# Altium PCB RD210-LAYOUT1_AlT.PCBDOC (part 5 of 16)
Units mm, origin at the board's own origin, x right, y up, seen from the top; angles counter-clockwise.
Board outline 330 x 300 mm, 6 copper layers (TOP, Mid-Layer 1, Mid-Layer 2, Mid-Layer 3, Mid-Layer 4, BOTTOM), stack 1.422 mm thick; 981 components, 463 nets, 2326 pads, 12534 vias.
Unrouted connection lines stored in the file: 6.
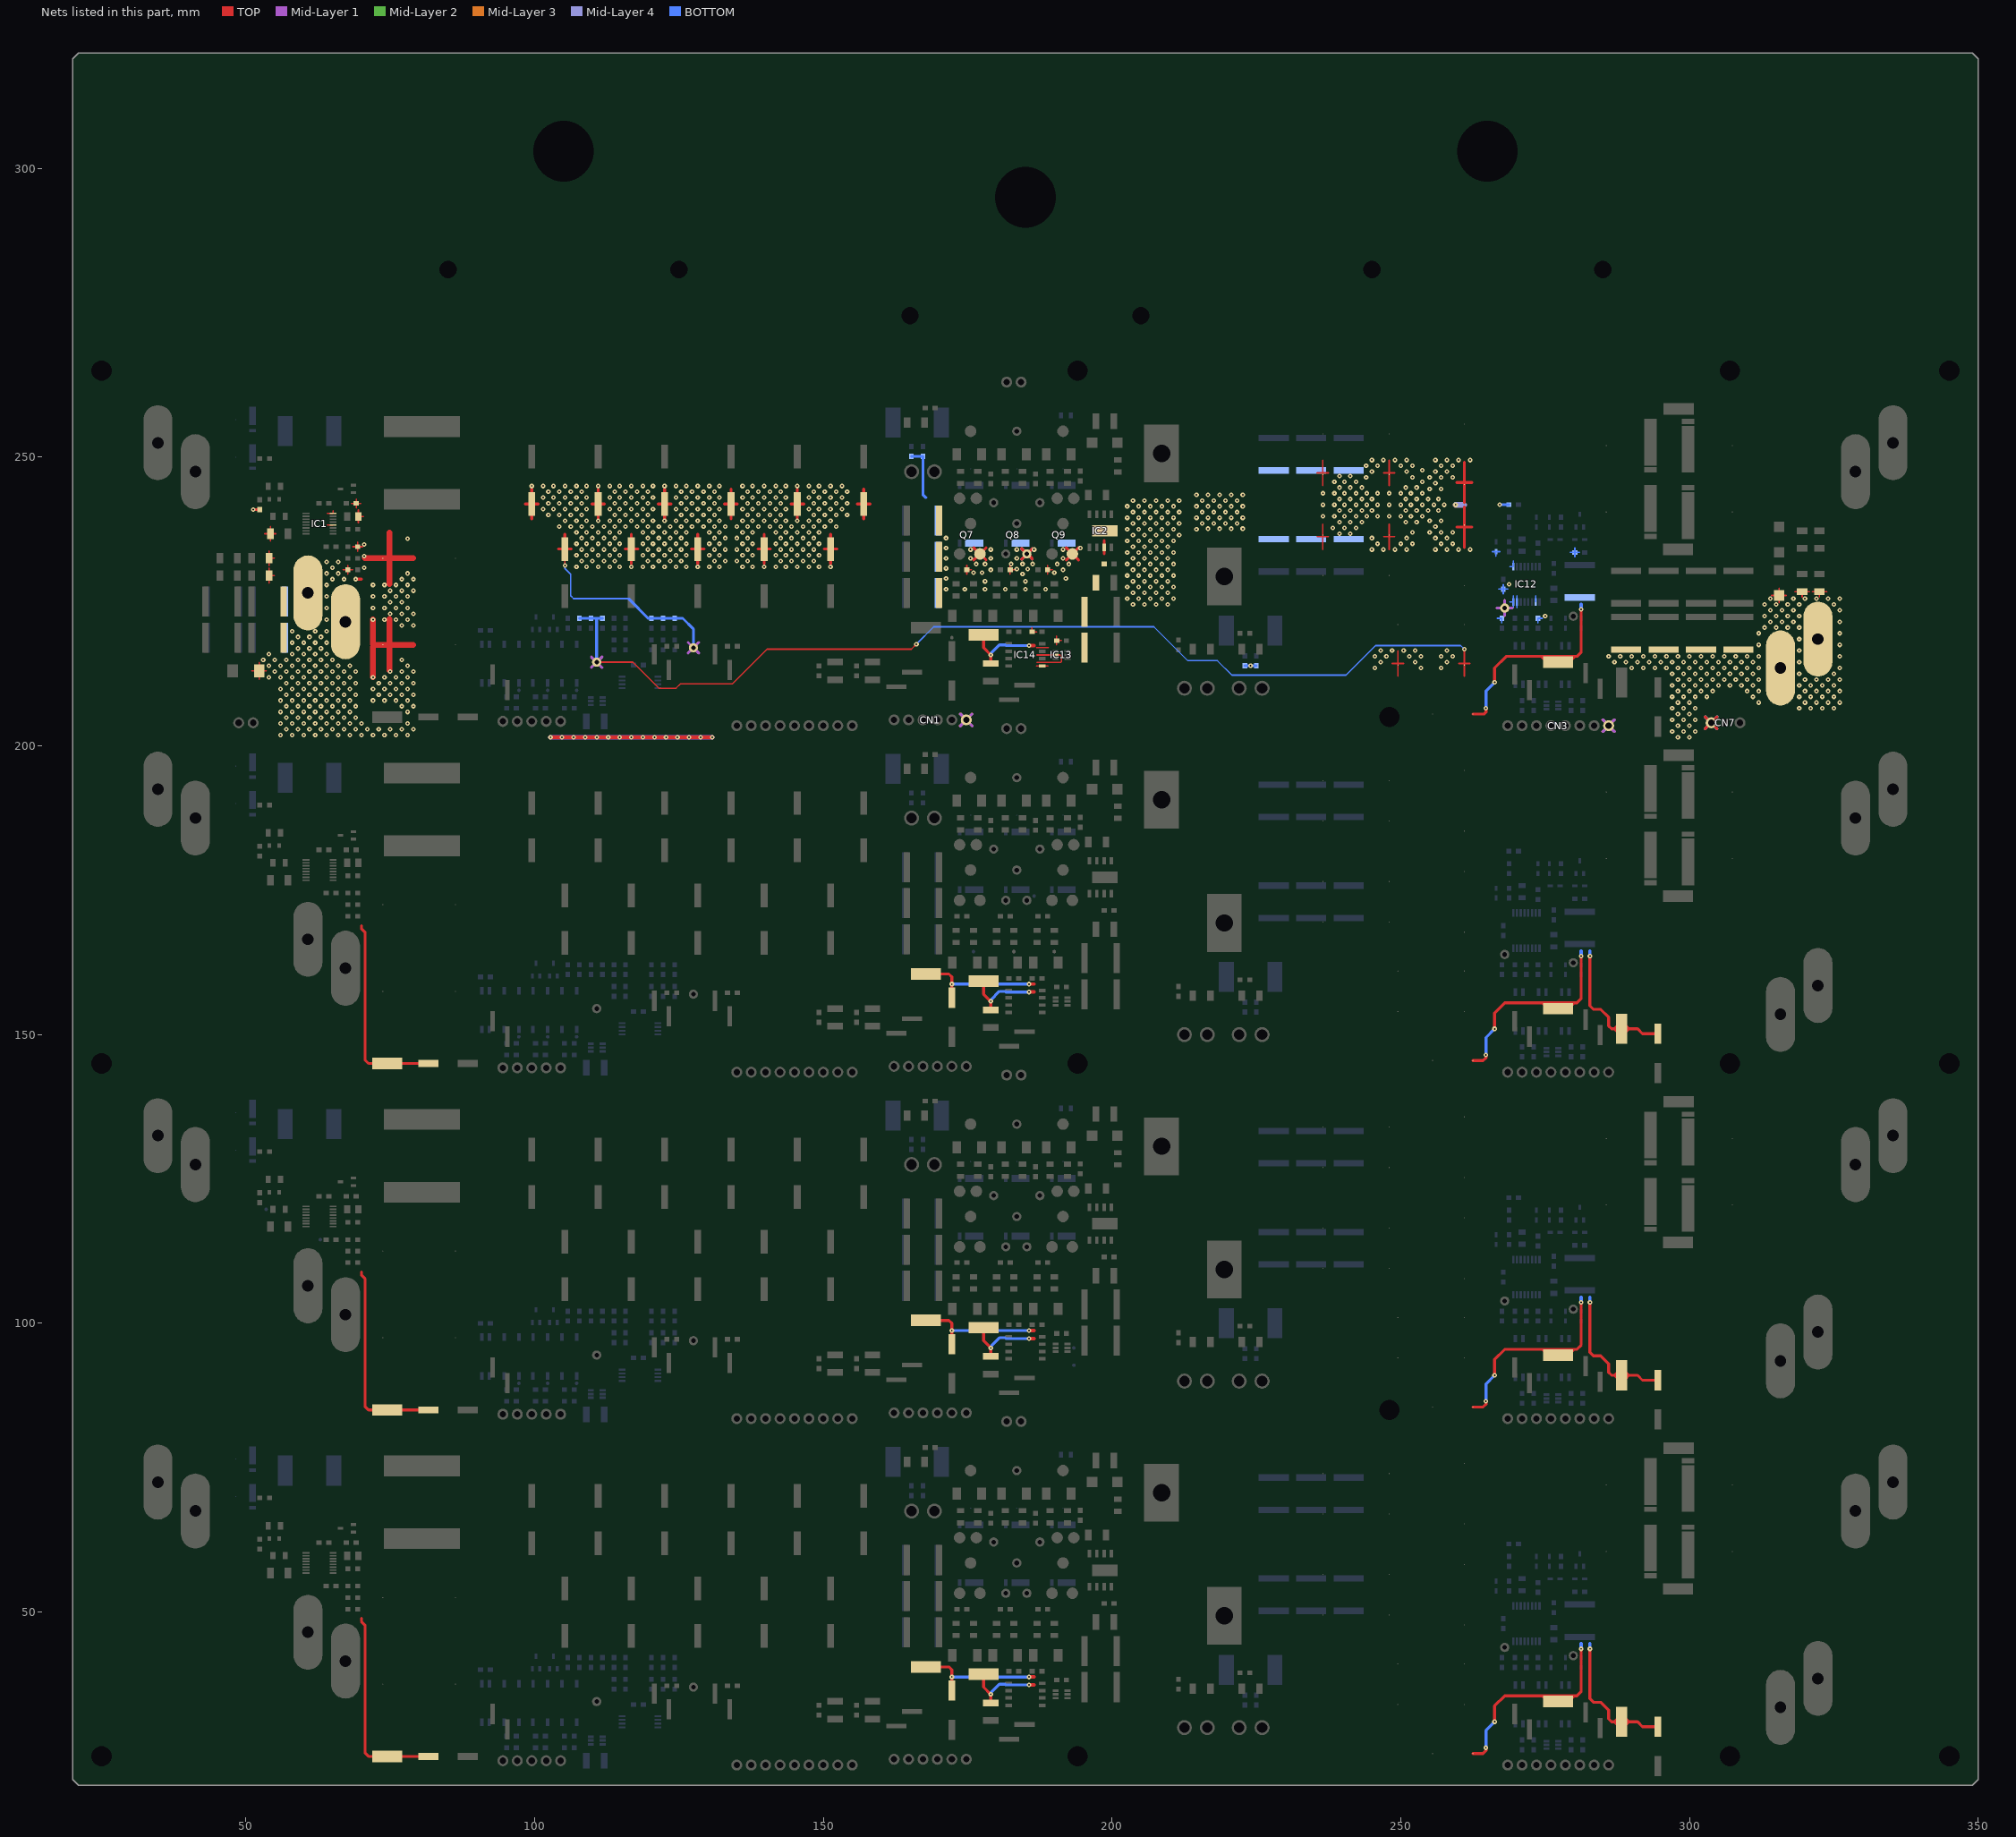
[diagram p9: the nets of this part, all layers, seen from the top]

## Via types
v1: diameter 0.8, hole 0.3, TOP to BOTTOM, 12534 vias

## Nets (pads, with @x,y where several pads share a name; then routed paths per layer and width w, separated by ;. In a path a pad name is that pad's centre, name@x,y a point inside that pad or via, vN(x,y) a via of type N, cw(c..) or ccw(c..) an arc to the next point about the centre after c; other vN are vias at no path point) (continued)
GND_5V_I1_0: C198.2 CN127.1 | length 22.6
  TOP w0.5: CN127.1@167.75,160.5 171.75,160.5 172.25,160 v1(172.25,158.75) C198.2@172.25,156.4
  TOP w0.6: v1(185.625,158.75) 186.5,158.75
  BOTTOM w0.5: v1(172.25,158.75) v1(185.625,158.75)
GND_5V_I1_1: C170.2 CN125.1 | length 32.8
  TOP w0.5: v1(282.75,163.625) 282.75,155 283.375,154.375 284.625,154.375 286,153 286,151.5 286.5,151 287,151 ; C170.2@294.5,150.15 291.85,150.15 291,151 289.5,151 ; 287,151 288,150 CN125.1@288.25,150 ; 287,151 288,152 CN125.1@288.25,152 ; 287,151 CN125.1@288.25,151 ; CN125.1@288.25,150 288.5,150 288.875,150.375 289.5,151 ; CN125.1@288.25,150 CN125.1@288.25,151 ; CN125.1@288.25,151 289.5,151 ; CN125.1@288.25,151 CN125.1@288.25,152 ; CN125.1@288.25,152 288.5,152 288.875,151.625 289.5,151
  BOTTOM w0.6: v1(282.75,163.625) 282.75,164.5
GND_5V_I1_2: C197.2 CN126.1 | length 34.7
  TOP w0.5: 70,168.875 70,168.375 70.625,167.75 70.625,145.625 71.25,145 CN126.1@74.5,145 C197.2@81.6,145
GND_5V_I2_0: C298.2 CN227.1 | length 22.6
  TOP w0.5: CN227.1@167.75,100.5 171.75,100.5 172.25,100 v1(172.25,98.75) C298.2@172.25,96.4
  TOP w0.6: v1(185.625,98.75) 186.5,98.75
  BOTTOM w0.5: v1(172.25,98.75) v1(185.625,98.75)
GND_5V_I2_1: C270.2 CN225.1 | length 32.8
  TOP w0.5: v1(282.75,103.625) 282.75,95 283.375,94.375 284.625,94.375 286,93 286,91.5 286.5,91 287,91 ; C270.2@294.5,90.15 291.85,90.15 291,91 289.5,91 ; 287,91 288,90 CN225.1@288.25,90 ; 287,91 288,92 CN225.1@288.25,92 ; 287,91 CN225.1@288.25,91 ; CN225.1@288.25,90 288.5,90 288.875,90.375 289.5,91 ; CN225.1@288.25,90 CN225.1@288.25,91 ; CN225.1@288.25,91 289.5,91 ; CN225.1@288.25,91 CN225.1@288.25,92 ; CN225.1@288.25,92 288.5,92 288.875,91.625 289.5,91
  BOTTOM w0.6: v1(282.75,103.625) 282.75,104.5
GND_5V_I2_2: C297.2 CN226.1 | length 34.7
  TOP w0.5: 70,108.875 70,108.375 70.625,107.75 70.625,85.625 71.25,85 CN226.1@74.5,85 C297.2@81.6,85
GND_5V_I3_0: C398.2 CN327.1 | length 22.6
  TOP w0.5: CN327.1@167.75,40.5 171.75,40.5 172.25,40 v1(172.25,38.75) C398.2@172.25,36.4
  TOP w0.6: v1(185.625,38.75) 186.5,38.75
  BOTTOM w0.5: v1(172.25,38.75) v1(185.625,38.75)
GND_5V_I3_1: C370.2 CN325.1 | length 32.8
  TOP w0.5: v1(282.75,43.625) 282.75,35 283.375,34.375 284.625,34.375 286,33 286,31.5 286.5,31 287,31 ; C370.2@294.5,30.15 291.85,30.15 291,31 289.5,31 ; 287,31 288,32 CN325.1@288.25,32 ; 287,31 287.625,30.375 288,30 CN325.1@288.25,30 ; 287,31 CN325.1@288.25,31 ; CN325.1@288.25,30 288.5,30 288.875,30.375 289.5,31 ; CN325.1@288.25,30 CN325.1@288.25,31 ; CN325.1@288.25,31 289.5,31 ; CN325.1@288.25,31 CN325.1@288.25,32 ; CN325.1@288.25,32 288.5,32 288.875,31.625 289.5,31
  BOTTOM w0.6: v1(282.75,43.625) 282.75,44.5
GND_5V_I3_2: C397.2 CN326.1 | length 34.7
  TOP w0.5: 70,48.875 70,48.375 70.625,47.75 70.625,25.625 71.25,25 CN326.1@74.5,25 C397.2@81.6,25
GND_12R0_SYS_I0_0: C99.2 CN28.1 | length 13.9
  TOP w0.5: CN28.1@177.75,219.25 177.75,217 v1(179,215.75) C99.2@179,214.275
  TOP w0.6: v1(185.625,217.375) 186.5,217.375
  BOTTOM w0.5: v1(179,215.75) 179,216 180.5,217.5 181.5,217.5 181.625,217.375 v1(185.625,217.375)
GND_12R0_SYS_I0_1: C71.2 CN24.1 | length 41.6
  TOP w0.5: C71.2@262.5,205.5 264.375,205.5 264.75,205.875 v1(264.75,206.5) ; v1(266.25,211) 266.25,213.5 268.25,215.5 274.375,215.5 ; v1(281.25,223.625) 281.25,216.25 280.5,215.5 280.125,215.5 ; 274.375,215.5 280.125,215.5 ; 274.375,215.5 275.375,214.5 CN24.1@277.25,214.5 279.125,214.5 280.125,215.5
  BOTTOM w0.5: v1(264.75,206.5) 264.75,209.5 v1(266.25,211)
  BOTTOM w0.6: v1(281.25,223.625) 281.25,224.5
GND_12R0_SYS_I1_0: C199.2 CN128.1 | length 13.9
  TOP w0.5: CN128.1@177.75,159.25 177.75,157 v1(179,155.75) C199.2@179,154.275
  TOP w0.6: v1(185.625,157.375) 186.5,157.375
  BOTTOM w0.5: v1(179,155.75) 179,156 180.5,157.5 181.5,157.5 181.625,157.375 v1(185.625,157.375)
GND_12R0_SYS_I1_1: C171.2 CN124.1 | length 41.4
  TOP w0.5: C171.2@262.5,145.5 264.25,145.5 264.75,146 v1(264.75,146.5) ; v1(266.25,151) 266.25,153.75 268,155.5 274.5,155.5 ; v1(281.25,163.625) 281.25,156.25 280.5,155.5 280,155.5 ; 274.5,155.5 280,155.5 ; 274.5,155.5 275.5,154.5 CN124.1@277.25,154.5 279,154.5 280,155.5
  BOTTOM w0.5: v1(264.75,146.5) 264.75,149.5 v1(266.25,151)
  BOTTOM w0.6: v1(281.25,163.625) 281.25,164.5
GND_12R0_SYS_I2_0: C299.2 CN228.1 | length 13.9
  TOP w0.5: CN228.1@177.75,99.25 177.75,97 v1(179,95.75) C299.2@179,94.275
  TOP w0.6: v1(185.625,97.375) 186.5,97.375
  BOTTOM w0.5: v1(179,95.75) 179,96 180.5,97.5 181.5,97.5 181.625,97.375 v1(185.625,97.375)
GND_12R0_SYS_I2_1: C271.2 CN224.1 | length 41.4
  TOP w0.5: C271.2@262.5,85.5 264.25,85.5 264.75,86 v1(264.75,86.5) ; v1(266.25,91) 266.25,93.75 268,95.5 274.5,95.5 ; v1(281.25,103.625) 281.25,96.25 280.5,95.5 280,95.5 ; 274.5,95.5 280,95.5 ; 274.5,95.5 275.5,94.5 CN224.1@277.25,94.5 279,94.5 280,95.5
  BOTTOM w0.5: v1(264.75,86.5) 264.75,89.5 v1(266.25,91)
  BOTTOM w0.6: v1(281.25,103.625) 281.25,104.5
GND_12R0_SYS_I3_0: C399.2 CN328.1 | length 13.9
  TOP w0.5: CN328.1@177.75,39.25 177.75,37 v1(179,35.75) C399.2@179,34.275
  TOP w0.6: v1(185.625,37.375) 186.5,37.375
  BOTTOM w0.5: v1(179,35.75) 179,36 180.5,37.5 181.5,37.5 181.625,37.375 v1(185.625,37.375)
GND_12R0_SYS_I3_1: C371.2 CN324.1 | length 41.4
  TOP w0.5: C371.2@262.5,25.5 264.25,25.5 264.75,26 v1(264.75,26.5) ; v1(266.25,31) 266.25,33.75 268,35.5 274.5,35.5 ; v1(281.25,43.625) 281.25,36.25 280.5,35.5 280,35.5 ; 274.5,35.5 280,35.5 ; 274.5,35.5 275.5,34.5 CN324.1@277.25,34.5 279,34.5 280,35.5
  BOTTOM w0.5: v1(264.75,26.5) 264.75,29.5 v1(266.25,31)
  BOTTOM w0.6: v1(281.25,43.625) 281.25,44.5
GND_P-1: C2.1 C4.1 C6.1 C8.1 C10.1 C12.1 C13.1 C14.2 C15.1 C16.2 C17.2 C18.2 C19.2 C20.2 C21.2 C22.2 C23.2 C24.2 C25.2 C26.2 C27.2 C28.2 C29.1 C30.1 C31.1 C32.1 C33.1 C34.1 C35.1 C36.1 C37.2 C38.2 C39.1 C40.1 C42.2 C43.2 C49.2 C50.2 C51.2 C52.2 C53.2 C54.2 C55.2 C56.2 C57.2 C58.2 C59.1 C60.1 C61.1 C62.1 C63.1 C64.1 C79.1 C81.1 C83.2 C86.1 C88.1 C90.1 C92.1 C94.1 C96.1 C101.1 C440.2 C444.2 CN1.6 CN3.1 CN7.3 CN16.1 CN17.1 CN20.1 CN34.1 D1.1 D16.1 D17.1 IC1.12 IC1.16 IC2.7 IC2.9 IC12.2 IC12.7 IC12.8 IC12.9 IC13.2 IC14.5 Q7.S Q8.S Q9.S R4.1 R22.2 R25.2 R28.2 R50.2 R51.1 R57.2 R58.1 R65.1 R88.1 R89.1 R93.1 TN12.1 TN12.2 TN14.1 TN14.2 TP17.1 TP19.1 | length 704.9
  TOP w0.25: 51.025,213 D1.1@52.3,213 ; 52.3,211.525 D1.1@52.3,213 ; 52.3,214.475 D1.1@52.3,213 ; 53.275,236.75 C13.1@54.225,236.75 ; 53.575,213 D1.1@52.3,213 ; 54.025,228.225 C4.1@54.025,229.5 ; 54.025,230.775 C4.1@54.025,229.5 ; 54.025,231.225 C2.1@54.025,232.5 ; 54.025,233.775 C2.1@54.025,232.5 ; 54.225,235.475 C13.1@54.225,236.75 ; 54.225,238.025 C13.1@54.225,236.75 ; 54.975,229.5 C4.1@54.025,229.5 ; 54.975,232.5 C2.1@54.025,232.5 ; 55.175,236.75 C13.1@54.225,236.75 ; 64.125,238.25 IC1.12@65.1,238.25 ; 64.125,240.25 IC1.16@65.1,240.25 65.1,240.76 ; 66.825,230.5 R4.1@67.65,230.5 ; 67.65,229.725 R4.1@67.65,230.5 ; 67.65,231.275 R4.1@67.65,230.5 ; 68.275,242 R65.1@69.1,242 ; 68.475,230.5 R4.1@67.65,230.5 ; 68.525,234.5 C15.1@69.35,234.5 ; 69.1,241.225 R65.1@69.1,242 ; 69.1,242.775 R65.1@69.1,242 ; 69.35,233.725 C15.1@69.35,234.5 ; 69.35,235.275 C15.1@69.35,234.5 ; 69.475,238.65 C14.2@69.475,239.75 ; 69.475,240.85 C14.2@69.475,239.75 ; 69.925,242 R65.1@69.1,242 ; 70.175,234.5 C15.1@69.35,234.5 ; 70.375,239.75 C14.2@69.475,239.75 ; v1(105.25,231.25) C28.2@105.25,234.1 ; CN17.1@110.75,214.5 117,214.5 121.5,210 124.5,210 125.25,210.75 134.25,210.75 140.25,216.75 165.25,216.75 v1(166.125,217.625) ; 174.85,229.725 R22.2@174.85,230.5 ; 174.85,231.275 R22.2@174.85,230.5 ; 175.675,230.5 R22.2@174.85,230.5 ; 182.35,229.725 R25.2@182.35,230.5 ; v1@182.35,231.275 R25.2@182.35,230.5 ; v1@183.175,230.5 R25.2@182.35,230.5 ; 186.15,220.525 C40.1@186.15,219.75 186.975,219.75 ; 186.875,217.02 189,217.02 ; 186.925,213.845 IC14.5@187.9,213.845 188.875,213.845 ; 187,214.48 191.105,214.48 191.215,214.59 191.215,215.515 190.98,215.75 IC13.2@190.225,215.75 187,215.75 ; 188.85,229.725 R28.2@188.85,230.5 ; 188.85,231.275 R28.2@188.85,230.5 ; 189.675,230.5 R28.2@188.85,230.5 ; 190.4,217.475 C39.1@190.4,218.25 ; 190.4,219.025 C39.1@190.4,218.25 ; 191.225,218.25 C39.1@190.4,218.25 ; 235.523,236.225 236.5,236.225 ; 235.523,247.275 236.5,247.275 ; 236.5,234.023 236.5,236.225 ; 236.5,238.427 C53.2@236.5,236.5 236.5,236.225 ; 236.5,245.073 C51.2@236.5,247 236.5,247.275 ; 236.5,249.477 236.5,247.275 ; 237.477,236.225 236.5,236.225 ; 237.477,247.275 236.5,247.275 ; 247.023,236.225 248,236.225 ; 247.023,247.275 248,247.275 ; 248,234.023 248,236.225 ; 248,238.427 C54.2@248,236.5 248,236.225 ; 248,245.073 C52.2@248,247 248,247.275 ; 248,249.477 248,247.275 ; 248.523,214.275 249.5,214.275 ; 248.977,236.225 248,236.225 ; 248.977,247.275 248,247.275 ; 249.5,212.073 C55.2@249.5,214 249.5,214.275 ; 249.5,216.477 249.5,214.275 ; 250.477,214.275 249.5,214.275 ; 260.023,214.275 261,214.275 ; 261,212.073 C56.2@261,214 261,214.275 ; v1(261,216.75) 261,214.275 ; 261.977,214.275 261,214.275 ; 314.225,226.05 D16.1@315.5,226.05 ; 315.5,224.775 D16.1@315.5,226.05 ; 315.5,227.325 D16.1@315.5,226.05 ; 316.775,226.05 D16.1@315.5,226.05 ; 318.225,226.725 C86.1@319.5,226.725 ; 319.5,225.775 C86.1@319.5,226.725 ; 320.775,226.725 C86.1@319.5,226.725 ; 321.225,226.725 C88.1@322.5,226.725 ; 322.5,225.775 C88.1@322.5,226.725 ; 323.775,226.725 C88.1@322.5,226.725
  TOP w0.5: v1(51.242,240.925) C444.2@52.385,240.925 ; v1(69,228.875) 70,228.875 ; 98.4,241.9 C18.2@99.5,241.9 ; 99.5,239.35 C18.2@99.5,241.9 ; 99.5,244.45 C18.2@99.5,241.9 ; 100.6,241.9 C18.2@99.5,241.9 ; 104.15,234.1 C28.2@105.25,234.1 ; 105.25,236.65 C28.2@105.25,234.1 ; 106.35,234.1 C28.2@105.25,234.1 ; 109.9,241.9 C19.2@111,241.9 ; v1@111,239.35 C19.2@111,241.9 ; 111,244.45 C19.2@111,241.9 ; 112.1,241.9 C19.2@111,241.9 ; 115.65,234.1 C27.2@116.75,234.1 ; 116.75,231.55 C27.2@116.75,234.1 ; 116.75,236.65 C27.2@116.75,234.1 ; 117.85,234.1 C27.2@116.75,234.1 ; 121.4,241.9 C20.2@122.5,241.9 ; v1@122.5,239.35 C20.2@122.5,241.9 ; 122.5,244.45 C20.2@122.5,241.9 ; 123.6,241.9 C20.2@122.5,241.9 ; 127.15,234.1 C26.2@128.25,234.1 ; 128.25,231.55 C26.2@128.25,234.1 ; 128.25,236.65 C26.2@128.25,234.1 ; 129.35,234.1 C26.2@128.25,234.1 ; 132.9,241.9 C21.2@134,241.9 ; 134,239.35 C21.2@134,241.9 ; 134,244.45 C21.2@134,241.9 ; 135.1,241.9 C21.2@134,241.9 ; 138.65,234.1 C25.2@139.75,234.1 ; 139.75,231.55 C25.2@139.75,234.1 ; 139.75,236.65 C25.2@139.75,234.1 ; 140.85,234.1 C25.2@139.75,234.1 ; 144.4,241.9 C22.2@145.5,241.9 ; v1@145.5,239.35 C22.2@145.5,241.9 ; 145.5,244.45 C22.2@145.5,241.9 ; 146.6,241.9 C22.2@145.5,241.9 ; 150.15,234.1 C24.2@151.25,234.1 ; 151.25,231.55 C24.2@151.25,234.1 ; 151.25,236.65 C24.2@151.25,234.1 ; 152.35,234.1 C24.2@151.25,234.1 ; 155.9,241.9 C23.2@157,241.9 ; 157,239.35 C23.2@157,241.9 ; 157,244.45 C23.2@157,241.9 ; 158.1,241.9 C23.2@157,241.9 ; 176.064,232.189 TP17.1@177.125,233.25 ; 176.064,234.311 TP17.1@177.125,233.25 ; 178.186,232.189 TP17.1@177.125,233.25 ; 178.186,234.311 TP17.1@177.125,233.25 ; 184.331,232.331 CN34.1@185.25,233.25 ; 184.331,234.169 CN34.1@185.25,233.25 ; CN34.1@185.375,233.25 186.125,232.5 ; 186.169,232.331 CN34.1@185.25,233.25 ; v1@186.169,234.169 CN34.1@185.25,233.25 ; 192.064,232.189 TP19.1@193.125,233.25 ; 192.064,234.311 TP19.1@193.125,233.25 ; 194.186,232.189 TP19.1@193.125,233.25 ; v1@194.186,234.311 TP19.1@193.125,233.25 ; 198.635,233.25 IC2.7@198.635,234.4 198.635,235.55 ; 259.696,237.9 261,237.9 ; 259.696,245.6 261,245.6 ; 261,234.396 261,237.9 ; 261,241.404 C58.2@261,238.25 261,237.9 ; 261,242.096 C57.2@261,245.25 261,245.6 ; 261,249.104 261,245.6 ; 262.304,237.9 261,237.9 ; 262.304,245.6 261,245.6 ; 302.725,202.975 CN7.3@303.75,204 ; 302.725,205.025 CN7.3@303.75,204 ; 304.775,202.975 CN7.3@303.75,204 ; 304.775,205.025 CN7.3@303.75,204
  TOP w0.6: v1(102.75,201.5) v1(104.75,201.5) v1(106.75,201.5) v1(108.75,201.5) v1(110.75,201.5) v1(112.75,201.5) v1(114.75,201.5) v1(116.75,201.5) v1(118.75,201.5) v1(120.75,201.5) v1(122.75,201.5) v1(124.75,201.5) v1(126.75,201.5) v1(128.75,201.5) v1(130.75,201.5)
  TOP w1: v1@70.625,232.5 C16.2@73.7,232.5 74.85,232.5 ; v1(72,211.875) 72,217.125 72.375,217.5 ; v1(72,221.875) 72,217.625 72.125,217.5 72.375,217.5 ; v1@74.85,213.043 74.85,217.5 ; 74.85,221.957 74.85,217.5 ; 74.85,228.043 74.85,232.5 ; 74.85,236.957 74.85,232.5 ; 79,217.5 74.85,217.5 ; 79,232.5 74.85,232.5 ; 72.375,217.5 C17.2@73.7,217.5 74.85,217.5
  Mid-Layer 1 w0.5: 109.831,213.581 CN17.1@110.75,214.5 ; 109.831,215.419 CN17.1@110.75,214.5 ; 111.669,213.581 CN17.1@110.75,214.5 ; 111.669,215.419 CN17.1@110.75,214.5 ; 126.581,216.081 CN16.1@127.5,217 ; 126.581,217.919 CN16.1@127.5,217 ; 128.419,216.081 CN16.1@127.5,217 ; 128.419,217.919 CN16.1@127.5,217 ; 173.725,203.475 CN1.6@174.75,204.5 ; 173.725,205.525 CN1.6@174.75,204.5 ; 175.775,203.475 CN1.6@174.75,204.5 ; 175.775,205.525 CN1.6@174.75,204.5 ; 184.331,232.331 CN34.1@185.25,233.25 ; 184.331,234.169 CN34.1@185.25,233.25 ; 186.169,232.331 CN34.1@185.25,233.25 ; v1@186.169,234.169 CN34.1@185.25,233.25 ; 266.7,223.875 CN20.1@268,223.875 ; 268,222.575 CN20.1@268,223.875 ; 268,225.175 CN20.1@268,223.875 ; 269.3,223.875 CN20.1@268,223.875 ; 284.975,202.475 CN3.1@286,203.5 ; 284.975,204.525 CN3.1@286,203.5 ; 287.025,202.475 CN3.1@286,203.5 ; 287.025,204.525 CN3.1@286,203.5 ; 302.725,202.975 CN7.3@303.75,204 ; 302.725,205.025 CN7.3@303.75,204 ; 304.775,202.975 CN7.3@303.75,204 ; 304.775,205.025 CN7.3@303.75,204
  Mid-Layer 1 w0.8: v1(102.75,201.5) v1(104.75,201.5) v1(106.75,201.5) v1(108.75,201.5) v1(110.75,201.5) v1(112.75,201.5) v1(114.75,201.5) v1(116.75,201.5) v1(118.75,201.5) v1(120.75,201.5) v1(122.75,201.5) v1(124.75,201.5) v1(126.75,201.5) v1(128.75,201.5) v1(130.75,201.5)
  Mid-Layer 2 w0.5: 173.725,203.475 CN1.6@174.75,204.5 ; 173.725,205.525 CN1.6@174.75,204.5 ; 175.775,203.475 CN1.6@174.75,204.5 ; 175.775,205.525 CN1.6@174.75,204.5 ; 184.331,232.331 CN34.1@185.25,233.25 ; 184.331,234.169 CN34.1@185.25,233.25 ; 186.169,232.331 CN34.1@185.25,233.25 ; v1@186.169,234.169 CN34.1@185.25,233.25 ; 266.7,223.875 CN20.1@268,223.875 ; 268,222.575 CN20.1@268,223.875 ; 268,225.175 CN20.1@268,223.875 ; 269.3,223.875 CN20.1@268,223.875 ; 284.975,202.475 CN3.1@286,203.5 ; 284.975,204.525 CN3.1@286,203.5 ; 287.025,202.475 CN3.1@286,203.5 ; 287.025,204.525 CN3.1@286,203.5 ; 302.725,202.975 CN7.3@303.75,204 ; 302.725,205.025 CN7.3@303.75,204 ; 304.775,202.975 CN7.3@303.75,204 ; 304.775,205.025 CN7.3@303.75,204
  Mid-Layer 3 w0.5: 173.725,203.475 CN1.6@174.75,204.5 ; 173.725,205.525 CN1.6@174.75,204.5 ; 175.775,203.475 CN1.6@174.75,204.5 ; 175.775,205.525 CN1.6@174.75,204.5 ; 184.331,232.331 CN34.1@185.25,233.25 ; 184.331,234.169 CN34.1@185.25,233.25 ; 186.169,232.331 CN34.1@185.25,233.25 ; v1@186.169,234.169 CN34.1@185.25,233.25 ; 266.7,223.875 CN20.1@268,223.875 ; 268,222.575 CN20.1@268,223.875 ; 268,225.175 CN20.1@268,223.875 ; 269.3,223.875 CN20.1@268,223.875 ; 284.975,202.475 CN3.1@286,203.5 ; 284.975,204.525 CN3.1@286,203.5 ; 287.025,202.475 CN3.1@286,203.5 ; 287.025,204.525 CN3.1@286,203.5 ; 302.725,202.975 CN7.3@303.75,204 ; 302.725,205.025 CN7.3@303.75,204 ; 304.775,202.975 CN7.3@303.75,204 ; 304.775,205.025 CN7.3@303.75,204
  Mid-Layer 4 w1: v1(259.5,241.75) 261,241.75
  BOTTOM w0.25: v1(105.25,231.25) 105.25,230.75 106.25,229.75 106.25,226 106.75,225.5 116.25,225.5 116.375,225.375 ; v1(166.125,217.625) 169.125,220.625 207.25,220.625 213.125,214.75 218.25,214.75 220.75,212.25 240.5,212.25 245.625,217.375 260.375,217.375 v1(261,216.75) ; 265.875,233.65 D17.1@266.5,233.65 ; 266.5,232.825 D17.1@266.5,233.65 ; 266.725,222.1 R88.1@267.5,222.1 267.5,221.275 ; 266.975,227.15 C83.2@267.75,227.15 ; 267.125,233.65 D17.1@266.5,233.65 ; 267.75,226.325 C83.2@267.75,227.15 ; 267.75,227.975 C83.2@267.75,227.15 ; 268.525,227.15 C83.2@267.75,227.15 ; 268.9,224.95 IC12.8@269.475,224.95 ; 268.9,231.05 IC12.9@269.475,231.05 269.475,232.075 ; 269.475,223.925 IC12.8@269.475,224.95 ; 269.475,225.975 IC12.8@269.475,224.95 ; 270.125,223.925 IC12.7@270.125,224.95 270.125,225.975 ; IC12.2@273.375,224.95 273.375,225.975 ; 273.75,221.275 R89.1@273.75,222.1 274.525,222.1 ; 279.325,233.5 R93.1@280.15,233.5 ; 280.15,232.725 R93.1@280.15,233.5 ; 280.15,234.275 R93.1@280.15,233.5 ; 280.975,233.5 R93.1@280.15,233.5
  BOTTOM w0.5: C79.1@107.75,222.1 R57.2@109.75,222.1 110.5,222.1 ; CN17.1@110.75,214.5 110.75,221.85 ; R58.1@111.75,222.1 111,222.1 ; 116.375,225.375 119.65,222.1 R51.1@120.25,222.1 C101.1@122.25,222.1 R50.2@124.25,222.1 125.65,222.1 127.5,220.25 CN16.1@127.5,217 ; C43.2@165.25,250.15 C42.2@167.25,250.15 167.25,243.5 167.75,243 ; 184.331,232.331 CN34.1@185.25,233.25 ; 184.331,234.169 CN34.1@185.25,233.25 ; 186.169,232.331 CN34.1@185.25,233.25 ; v1@186.169,234.169 CN34.1@185.25,233.25 ; C49.2@223,213.9 v1(224,213.9) C50.2@225,213.9 ; 266.7,223.875 CN20.1@268,223.875 268,225.175 ; v1(267.142,241.775) C440.2@268.705,241.775 ; 110.5,222.1 110.75,221.85 ; 110.5,222.1 111,222.1 ; 110.75,221.85 111,222.1
  BOTTOM w0.6: v1(102.75,201.5) v1(104.75,201.5) v1(106.75,201.5) v1(108.75,201.5) v1(110.75,201.5) v1(112.75,201.5) v1(114.75,201.5) v1(116.75,201.5) v1(118.75,201.5) v1(120.75,201.5) v1(122.75,201.5) v1(124.75,201.5) v1(126.75,201.5) v1(128.75,201.5) v1(130.75,201.5)
  other v1: 298,201.5 300,201.5 56,201.875 58,201.875 60,201.875 62,201.875 64,201.875 66,201.875 68,201.875 70,201.875 72,201.875 74,201.875 76,201.875 78,201.875 297,202.5 299,202.5 301,202.5 57,202.875 59,202.875 61,202.875 63,202.875 65,202.875 67,202.875 69,202.875 71,202.875 73,202.875 75,202.875 77,202.875 79,202.875 298,203.5 300,203.5 56,203.875 58,203.875 60,203.875 62,203.875 64,203.875 66,203.875 68,203.875 70,203.875 78,203.875 297,204.5 299,204.5 301,204.5 57,204.875 59,204.875 61,204.875 63,204.875 65,204.875 67,204.875 69,204.875 298,205.5 300,205.5 56,205.875 58,205.875 60,205.875 62,205.875 64,205.875 66,205.875 68,205.875 78,205.875 297,206.5 299,206.5 301,206.5 319,206.5 321,206.5 323,206.5 325,206.5 57,206.875 59,206.875 61,206.875 63,206.875 65,206.875 67,206.875 69,206.875 77,206.875 79,206.875 298,207.5 300,207.5 312,207.5 320,207.5 322,207.5 324,207.5 326,207.5 56,207.875 58,207.875 60,207.875 62,207.875 64,207.875 66,207.875 68,207.875 72,207.875 74,207.875 76,207.875 78,207.875 297,208.5 299,208.5 301,208.5 303,208.5 311,208.5 319,208.5 321,208.5 323,208.5 325,208.5 57,208.875 59,208.875 61,208.875 63,208.875 65,208.875 67,208.875 69,208.875 73,208.875 75,208.875 77,208.875 79,208.875 298,209.5 300,209.5 302,209.5 304,209.5 310,209.5 312,209.5 320,209.5 322,209.5 324,209.5 326,209.5 56,209.875 58,209.875 60,209.875 62,209.875 64,209.875 66,209.875 68,209.875 72,209.875 74,209.875 76,209.875 78,209.875 297,210.5 299,210.5 301,210.5 303,210.5 305,210.5 307,210.5 309,210.5 311,210.5 319,210.5 321,210.5 323,210.5 325,210.5 57,210.875 59,210.875 61,210.875 63,210.875 65,210.875 67,210.875 69,210.875 73,210.875 75,210.875 77,210.875 79,210.875 298,211.5 300,211.5 302,211.5 304,211.5 306,211.5 308,211.5 310,211.5 312,211.5 320,211.5 322,211.5 324,211.5 326,211.5 54,211.875 56,211.875 58,211.875 60,211.875 62,211.875 64,211.875 66,211.875 68,211.875 74,211.875 76,211.875 78,211.875 297,212.5 299,212.5 301,212.5 303,212.5 305,212.5 307,212.5 309,212.5 311,212.5 319,212.5 325,212.5 55,212.875 57,212.875 59,212.875 61,212.875 63,212.875 65,212.875 67,212.875 69,212.875 75,212.875 77,212.875 79,212.875 245.5,213.5 253.5,213.5 257,213.5 290,213.5 292,213.5 294,213.5 296,213.5 298,213.5 300,213.5 302,213.5 304,213.5 306,213.5 308,213.5 310,213.5 312,213.5 326,213.5 54,213.875 56,213.875 58,213.875 60,213.875 62,213.875 64,213.875 66,213.875 68,213.875 78,213.875 246.5,214.5 252.5,214.5 258,214.5 287,214.5 289,214.5 291,214.5 293,214.5 295,214.5 297,214.5 299,214.5 301,214.5 303,214.5 305,214.5 307,214.5 309,214.5 311,214.5 319,214.5 53,214.875 55,214.875 57,214.875 59,214.875 61,214.875 63,214.875 65,214.875 77,214.875 245.5,215.5 247.5,215.5 251.5,215.5 253.5,215.5 257,215.5 259,215.5 286,215.5 288,215.5 290,215.5 292,215.5 294,215.5 296,215.5 298,215.5 300,215.5 302,215.5 304,215.5 306,215.5 308,215.5 310,215.5 312,215.5 326,215.5 54,215.875 58,215.875 60,215.875 62,215.875 64,215.875 246.5,216.5 248.5,216.5 250.5,216.5 252.5,216.5 258,216.5 319,216.5 59,216.875 61,216.875 63,216.875 312,217.5 326,217.5 58,217.875 60,217.875 62,217.875 64,217.875 319,218.5 59,218.875 61,218.875 63,218.875 312,219.5 326,219.5 58,219.875 62,219.875 64,219.875 313,220.5 315,220.5 317,220.5 319,220.5 77,220.875 79,220.875 314,221.5 316,221.5 318,221.5 326,221.5 64,221.875 74,221.875 76,221.875 78,221.875 275,222.5 313,222.5 315,222.5 317,222.5 319,222.5 75,222.875 77,222.875 79,222.875 314,223.5 316,223.5 318,223.5 326,223.5 64,223.875 72,223.875 74,223.875 76,223.875 78,223.875 203.625,224.5 205.625,224.5 207.625,224.5 209.625,224.5 313,224.5 315,224.5 317,224.5 319,224.5 325,224.5 75,224.875 77,224.875 202.625,225.5 204.625,225.5 206.625,225.5 208.625,225.5 210.625,225.5 314,225.5 318,225.5 320,225.5 322,225.5 324,225.5 326,225.5 64,225.875 72,225.875 74,225.875 76,225.875 78,225.875 203.625,226.5 205.625,226.5 207.625,226.5 209.625,226.5 75,226.875 77,226.875 79,226.875 171.25,227.125 174.5,227.125 178,227.125 181.5,227.125 185,227.125 188.5,227.125 202.625,227.5 204.625,227.5 206.625,227.5 208.625,227.5 210.625,227.5 64,227.875 72,227.875 74,227.875 76,227.875 78,227.875 268.75,228 178,228.5 185,228.5 203.625,228.5 205.625,228.5 207.625,228.5 209.625,228.5 65,228.875 67,228.875 77,228.875 79,228.875 171.25,229 192,229 202.625,229.5 204.625,229.5 206.625,229.5 208.625,229.5 210.625,229.5 184.5,229.75 64,229.875 66,229.875 78,229.875 176,230 177.5,230 190,230 179,230.5 191.5,230.5 203.625,230.5 205.625,230.5 207.625,230.5 209.625,230.5 183.5,230.625 185.375,230.625 171.25,230.75 65,230.875 70.5,230.875 107.25,231 109,231 111,231 113,231 114.75,231 116.75,231 118.75,231 120.5,231 122.5,231 124.5,231 126.25,231 128.25,231 130.25,231 132,231 136,231 137.75,231 139.75,231 141.75,231 143.5,231 145.5,231 147.5,231 149.25,231 151.25,231 176.5,231.5 178,231.5 182.5,231.5 184.5,231.5 186.25,231.5 190.5,231.5 192.5,231.5 202.625,231.5 204.625,231.5 206.625,231.5 208.625,231.5 210.625,231.5 64,231.875 66,231.875 108.125,232 110,232 112,232 113.875,232 119.625,232 121.5,232 123.5,232 125.375,232 131.125,232 133,232 135,232 136.875,232 142.625,232 144.5,232 146.5,232 148.375,232 171.25,232.5 175.5,232.5 179,232.5 183.5,232.5 191.5,232.5 203.625,232.5 205.625,232.5 207.625,232.5 209.625,232.5 70.5,232.875 107.25,233 109,233 111,233 113,233 114.75,233 118.75,233 120.5,233 122.5,233 124.5,233 126.25,233 130.25,233 132,233 136,233 137.75,233 141.75,233 143.5,233 145.5,233 147.5,233 149.25,233 202.625,233.5 204.625,233.5 206.625,233.5 208.625,233.5 210.625,233.5 108.125,234 110,234 112,234 113.875,234 119.625,234 121.5,234 123.5,234 125.375,234 131.125,234 133,234 135,234 136.875,234 142.625,234 144.5,234 146.5,234 148.375,234 175.5,234 179,234 183.5,234 186.5,234 191.5,234 245,234 247,234 249,234 251,234 256,234 258,234 260,234 262,234 171.25,234.25 194.5,234.25 203.625,234.5 205.625,234.5 207.625,234.5 209.625,234.5 70.5,234.875 107.25,235 109,235 111,235 113,235 114.75,235 118.75,235 120.5,235 122.5,235 124.5,235 126.25,235 130.25,235 132,235 136,235 137.75,235 141.75,235 143.5,235 145.5,235 147.5,235 149.25,235 246,235 250,235 252,235 257,235 259,235 202.625,235.5 204.625,235.5 206.625,235.5 208.625,235.5 210.625,235.5 78,235.875 108.125,236 110,236 112,236 113.875,236 119.625,236 121.5,236 123.5,236 125.375,236 131.125,236 133,236 135,236 136.875,236 142.625,236 144.5,236 146.5,236 148.375,236 171.25,236 245,236 251,236 256,236 258,236 203.625,236.5 205.625,236.5 207.625,236.5 209.625,236.5 211.625,236.5 239.375,236.75 241.25,236.75 107.25,237 109,237 111,237 113,237 114.75,237 118.75,237 120.5,237 122.5,237 124.5,237 126.25,237 130.25,237 132,237 136,237 137.75,237 141.75,237 143.5,237 145.5,237 147.5,237 149.25,237 252,237 255,237 257,237 259,237 202.625,237.5 204.625,237.5 206.625,237.5 208.625,237.5 210.625,237.5 214.625,237.5 216.625,237.625 218.625,237.625 220.625,237.625 222.625,237.625 238.25,237.75 240.25,237.75 242.25,237.75 104.25,238 106.25,238 108.125,238 110,238 112,238 113.875,238 115.75,238 117.75,238 119.625,238 121.5,238 123.5,238 125.375,238 127.25,238 129.25,238 131.125,238 133,238 135,238 136.875,238 138.75,238 140.75,238 142.625,238 144.5,238 146.5,238 148.375,238 150.25,238 152.25,238 256,238 203.625,238.5 205.625,238.5 207.625,238.5 209.625,238.5 211.625,238.5 215.625,238.5 217.625,238.5 219.625,238.5 221.625,238.5 239.375,238.75 241.25,238.75 243.25,238.75 250.875,238.75 252.75,238.75 105.25,239 107.25,239 109,239 111,239 113,239 114.75,239 116.75,239 118.75,239 120.5,239 122.5,239 124.5,239 126.25,239 128.25,239 130.25,239 132,239 136,239 137.75,239 139.75,239 141.75,239 143.5,239 145.5,239 147.5,239 149.25,239 151.25,239 255,239 257,239 202.625,239.5 204.625,239.5 206.625,239.5 208.625,239.5 210.625,239.5 214.625,239.5 216.625,239.5 218.625,239.5 220.625,239.5 222.625,239.5 236.5,239.75 238.5,239.75 240.25,239.75 242.25,239.75 244.125,239.75 246,239.75 248,239.75 250,239.75 251.75,239.75 253.75,239.75 102.375,240 104.25,240 106.25,240 108.125,240 113.875,240 115.75,240 117.75,240 119.625,240 125.375,240 127.25,240 129.25,240 131.125,240 136.875,240 138.75,240 140.75,240 142.625,240 148.375,240 150.25,240 152.25,240 154.125,240 203.625,240.5 205.625,240.5 207.625,240.5 209.625,240.5 211.625,240.5 215.625,240.5 217.625,240.5 219.625,240.5 221.625,240.5 239.375,240.75 241.25,240.75 243.25,240.75 245,240.75 250.875,240.75 252.75,240.75 254.75,240.75 256.5,240.75 101.5,241 103.25,241 105.25,241 107.25,241 109,241 113,241 114.75,241 116.75,241 118.75,241 120.5,241 124.5,241 126.25,241 128.25,241 130.25,241 132,241 136,241 137.75,241 139.75,241 141.75,241 143.5,241 147.5,241 149.25,241 151.25,241 153.25,241 202.625,241.5 204.625,241.5 206.625,241.5 208.625,241.5 210.625,241.5 214.625,241.5 216.625,241.5 218.625,241.5 220.625,241.5 222.625,241.5 236.5,241.75 238.5,241.75 240.25,241.75 242.25,241.75 244.125,241.75 246,241.75 248,241.75 250,241.75 251.75,241.75 253.75,241.75 255.75,241.75 257.5,241.75 102.375,242 104.25,242 106.25,242 108.125,242 113.875,242 115.75,242 117.75,242 119.625,242 125.375,242 127.25,242 129.25,242 131.125,242 136.875,242 138.75,242 140.75,242 142.625,242 148.375,242 150.25,242 152.25,242 154.125,242 203.625,242.5 205.625,242.5 207.625,242.5 209.625,242.5 211.625,242.5 215.625,242.5 217.625,242.5 219.625,242.5 221.625,242.5 239.375,242.75 241.25,242.75 243.25,242.75 245,242.75 250.875,242.75 252.75,242.75 254.75,242.75 256.5,242.75 101.5,243 103.25,243 105.25,243 107.25,243 109,243 113,243 114.75,243 116.75,243 118.75,243 120.5,243 124.5,243 126.25,243 128.25,243 130.25,243 132,243 136,243 137.75,243 139.75,243 141.75,243 143.5,243 147.5,243 149.25,243 151.25,243 153.25,243 214.625,243.5 216.625,243.5 218.625,243.5 220.625,243.5 222.625,243.5 236.5,243.75 238.5,243.75 240.25,243.75 242.25,243.75 244.125,243.75 246,243.75 248,243.75 250,243.75 251.75,243.75 253.75,243.75 102.375,244 104.25,244 106.25,244 108.125,244 113.875,244 115.75,244 117.75,244 119.625,244 125.375,244 127.25,244 129.25,244 131.125,244 136.875,244 138.75,244 140.75,244 142.625,244 148.375,244 150.25,244 152.25,244 154.125,244 255,244.5 257,244.5 239.375,244.75 241.25,244.75 243.25,244.75 250.875,244.75 252.75,244.75 99.5,245 101.5,245 103.25,245 105.25,245 107.25,245 109,245 111,245 113,245 114.75,245 116.75,245 118.75,245 120.5,245 122.5,245 124.5,245 126.25,245 128.25,245 130.25,245 132,245 136,245 137.75,245 139.75,245 141.75,245 143.5,245 145.5,245 147.5,245 149.25,245 151.25,245 153.25,245 256,245.5 238.5,245.75 240.25,245.75 242.25,245.75 253.75,245.75 244,246.5 252,246.5 255,246.5 257,246.5 259,246.5 239.375,246.75 241.25,246.75 245,247.5 251,247.5 256,247.5 258,247.5 253.75,247.75 244,248.5 246,248.5 250,248.5 252,248.5 257,248.5 259,248.5 245,249.5 247,249.5 249,249.5 251,249.5 256,249.5 258,249.5 260,249.5 262,249.5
